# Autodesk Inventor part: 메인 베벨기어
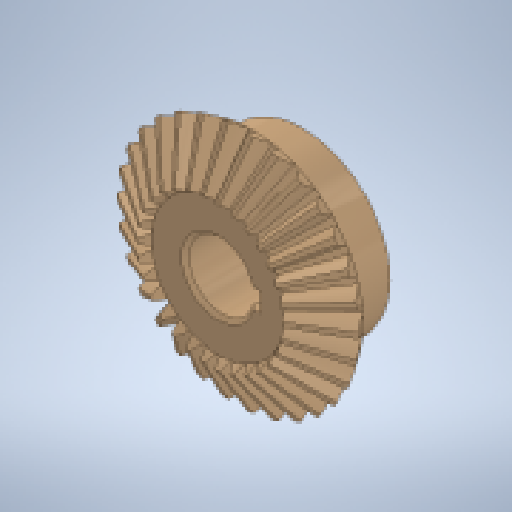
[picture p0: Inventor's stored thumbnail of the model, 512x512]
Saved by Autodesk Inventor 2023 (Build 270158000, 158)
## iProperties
Created: 2025-04
Part Number: 메인 베벨기어
Material: 강철, 탄소
Document SubType Name: Modeling
Designer: user
Density: 7.87 g/cm^3
Appearance: 기본값
Author: jhkim
Revision Number: 1
Sending System: Autodesk Inventor 2026
Preprocessor: ST-DEVELOPER v20.1
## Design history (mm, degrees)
feature "Solid1"
node "솔리드1"
